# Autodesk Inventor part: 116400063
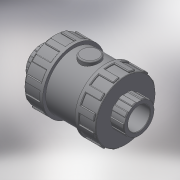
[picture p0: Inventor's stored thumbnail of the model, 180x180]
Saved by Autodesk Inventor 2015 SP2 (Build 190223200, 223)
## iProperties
Created: 2017-11
Part Number: 116400063
Material: Generic
Description: PLASSON FOOT VALVE CEM PVC 63
Document SubType Name: Modeling
Designer: KIM
Density: 1 g/cm^3
Appearance: Default
Author: KIM
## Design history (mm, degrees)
derived "116400 - 116000.ipt"
feature "Solid1::116400 - 116000.ipt"
tag "TaggingFeature1"
body "Solid1"
other parameters: "d0" = 169, "d1" = 63, "d2" = 118, "d3" = 38, "d4" = 50.4, "d5" = 26.6, "d7" = 88.2, "d8" = 106.2, "d13" = 1.89, "d23" = 38, "d24" = 113.28, "d25" = 1.26, "d26" = 1.89, "d27" = 17.7, "d28" = 8.85, "d29" = 28.5, "d30" = 0, "d35" = 1.89, "d39" = 59, "d45" = 360 deg, "d47" = 1.26, "d50" = 59, "d51" = 35.4, "d53" = 0, "d54" = 2.36, "d56" = 12.6, "d57" = 6.3, "d59" = 0, "d60" = 1.89, "d62" = 360 deg, "d_" = 63, "l_" = 38, "H_" = 169, "K_" = 118
